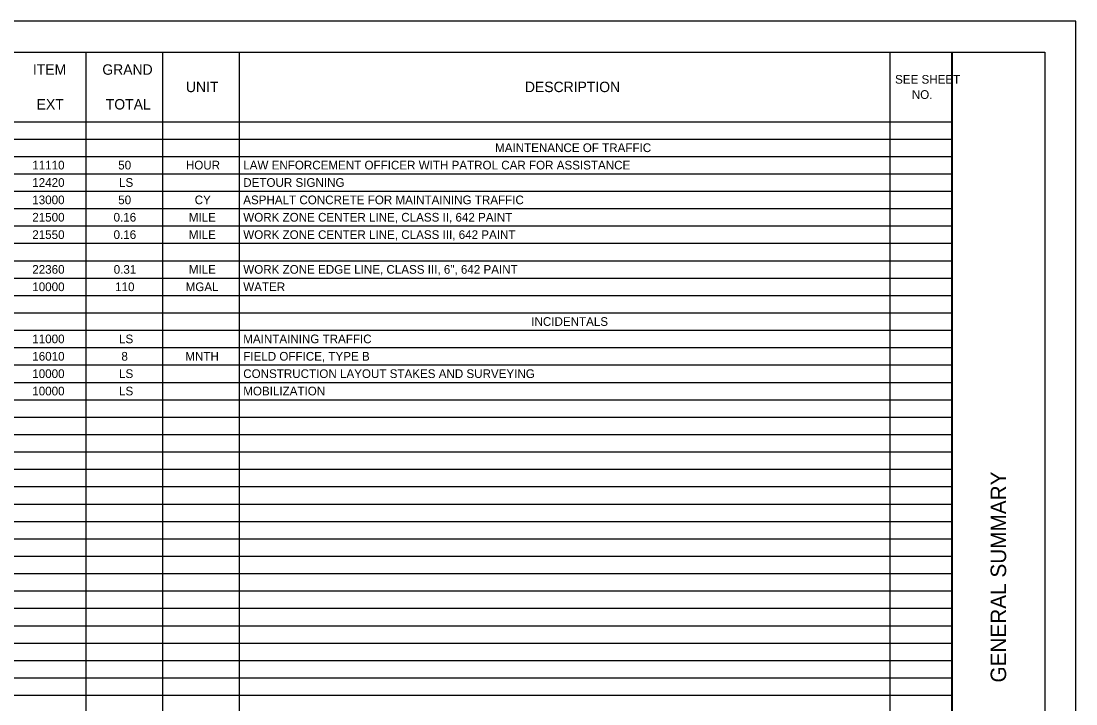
# Model space of a CAD drawing. Extents: x 0 to 34, y 0 to 22.
# Drawn here: x 16.99 to 34, y 11 to 22 of the extents above; entities that cross this region are included whole.
import ezdxf

# ---------------------------------------------------------------- set-up
doc = ezdxf.new("R2010")
doc.units = 0
for name, color, linetype in [('SH_Border', 7, 'Continuous'), ('SH_Cut_Line', 7, 'Continuous'), ('SH_Data', 7, 'Continuous'), ('SH_Text', 7, 'Continuous')]:
    doc.layers.add(name, color=color, linetype=linetype)

msp = doc.modelspace()

# ---------------------------------------------------------------- linework, layer by layer
at = {"layer": 'SH_Border'}
msp.add_line((32, 0.5), (32, 21.5), dxfattribs=at)
msp.add_lwpolyline([(1.5, 21.5), (33.5, 21.5), (33.5, 0.5), (1.5, 0.5)], close=True, dxfattribs=at)
at = {"layer": 'SH_Cut_Line'}
msp.add_lwpolyline([(0, 0), (34, 0), (34, 22), (0, 22)], close=True, dxfattribs=at)
at = {"layer": 'SH_Data'}
for p, q in [((1.5, 21.5), (32.004, 21.5)), ((18.036, 21.5), (18.036, 0.5)), ((19.272, 21.5), (19.272, 0.5)), ((20.507, 21.5), (20.507, 0.5)), ((30.999, 21.5), (30.999, 0.5)), ((32.004, 21.5), (32.004, 0.5)), ((1.5, 20.38), (32.004, 20.38)), ((1.5, 20.1), (32.004, 20.1)), ((1.5, 19.82), (32.004, 19.82)), ((1.5, 19.54), (32.004, 19.54)), ((1.5, 19.26), (32.004, 19.26)), ((1.5, 18.98), (32.004, 18.98)), ((1.5, 18.7), (32.004, 18.7)), ((1.5, 18.42), (32.004, 18.42)), ((1.5, 18.14), (32.004, 18.14)), ((1.5, 17.86), (32.004, 17.86)), ((1.5, 17.58), (32.004, 17.58)), ((1.5, 17.3), (32.004, 17.3)), ((1.5, 17.02), (32.004, 17.02)), ((1.5, 16.74), (32.004, 16.74)), ((1.5, 16.46), (32.004, 16.46)), ((1.5, 16.18), (32.004, 16.18)), ((1.5, 15.9), (32.004, 15.9)), ((1.5, 15.62), (32.004, 15.62)), ((1.5, 15.34), (32.004, 15.34)), ((1.5, 15.06), (32.004, 15.06)), ((1.5, 14.78), (32.004, 14.78)), ((1.5, 14.5), (32.004, 14.5)), ((1.5, 14.22), (32.004, 14.22)), ((1.5, 13.94), (32.004, 13.94)), ((1.5, 13.66), (32.004, 13.66)), ((1.5, 13.38), (32.004, 13.38)), ((1.5, 13.1), (32.004, 13.1)), ((1.5, 12.82), (32.004, 12.82)), ((1.5, 12.54), (32.004, 12.54)), ((1.5, 12.26), (32.004, 12.26)), ((1.5, 11.98), (32.004, 11.98)), ((1.5, 11.7), (32.004, 11.7)), ((1.5, 11.42), (32.004, 11.42)), ((1.5, 11.14), (32.004, 11.14))]:
    msp.add_line(p, q, dxfattribs=at)

# ---------------------------------------------------------------- texts
msp.add_text('GENERAL SUMMARY', height=0.25, rotation=90, dxfattribs=at).set_placement((32.875, 11.344))
at = {"layer": 'SH_Text'}
for s, height, p in [('ITEM', 0.168, (17.181, 21.136)), ('GRAND', 0.168, (18.301, 21.136)), ('SEE SHEET ', 0.14, (31.084, 20.992)), ('UNIT', 0.168, (19.649, 20.856)), ('DESCRIPTION', 0.168, (25.115, 20.856)), ('NO.', 0.14, (31.354, 20.747)), ('EXT', 0.168, (17.242, 20.576)), ('TOTAL', 0.168, (18.357, 20.576)), ('MAINTENANCE OF TRAFFIC', 0.14, (24.634, 19.89)), ('11110', 0.14, (17.171, 19.61)), ('50', 0.14, (18.557, 19.61)), ('HOUR', 0.14, (19.648, 19.61)), ('LAW ENFORCEMENT OFFICER WITH PATROL CAR FOR ASSISTANCE', 0.14, (20.573, 19.61)), ('12420', 0.14, (17.171, 19.33)), ('LS', 0.14, (18.57, 19.33)), ('DETOUR SIGNING', 0.14, (20.573, 19.33)), ('13000', 0.14, (17.171, 19.05)), ('50', 0.14, (18.557, 19.05)), ('CY', 0.14, (19.79, 19.05)), ('ASPHALT CONCRETE FOR MAINTAINING TRAFFIC', 0.14, (20.573, 19.05)), ('21500', 0.14, (17.171, 18.77)), ('0.16', 0.14, (18.482, 18.77)), ('MILE', 0.14, (19.695, 18.77)), ('WORK ZONE CENTER LINE, CLASS II, 642 PAINT', 0.14, (20.573, 18.77)), ('21550', 0.14, (17.171, 18.49)), ('0.16', 0.14, (18.482, 18.49)), ('MILE', 0.14, (19.695, 18.49)), ('WORK ZONE CENTER LINE, CLASS III, 642 PAINT', 0.14, (20.573, 18.49)), ('22360', 0.14, (17.171, 17.93)), ('0.31', 0.14, (18.484, 17.93)), ('MILE', 0.14, (19.695, 17.93)), ('WORK ZONE EDGE LINE, CLASS III, 6", 642 PAINT', 0.14, (20.573, 17.93)), ('10000', 0.14, (17.171, 17.65)), ('110', 0.14, (18.507, 17.65)), ('MGAL', 0.14, (19.644, 17.65)), ('WATER', 0.14, (20.573, 17.65)), ('INCIDENTALS', 0.14, (25.218, 17.09)), ('11000', 0.14, (17.171, 16.81)), ('LS', 0.14, (18.57, 16.81)), ('MAINTAINING TRAFFIC', 0.14, (20.573, 16.81)), ('16010', 0.14, (17.171, 16.53)), ('8', 0.14, (18.608, 16.53)), ('MNTH', 0.14, (19.639, 16.53)), ('FIELD OFFICE, TYPE B', 0.14, (20.573, 16.53)), ('10000', 0.14, (17.171, 16.25)), ('LS', 0.14, (18.57, 16.25)), ('CONSTRUCTION LAYOUT STAKES AND SURVEYING', 0.14, (20.573, 16.25)), ('10000', 0.14, (17.171, 15.97)), ('LS', 0.14, (18.57, 15.97)), ('MOBILIZATION', 0.14, (20.573, 15.97))]:
    msp.add_text(s, height=height, dxfattribs=at).set_placement(p)

doc.saveas('drawing.dxf')
